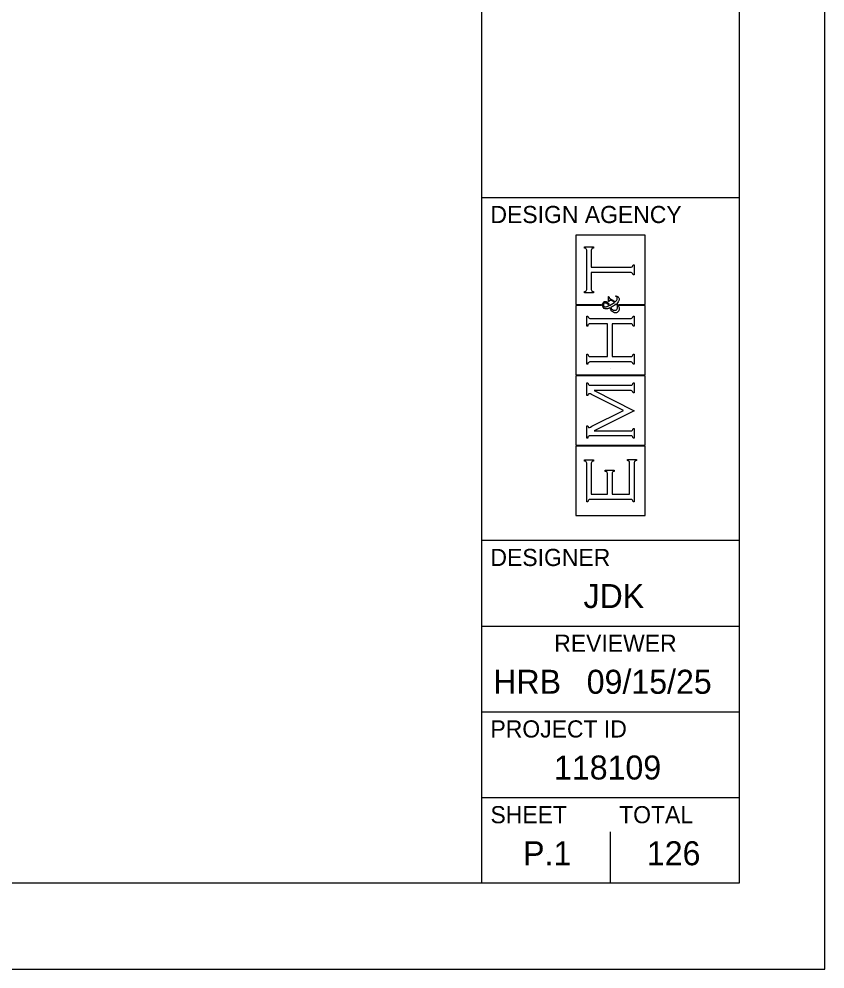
# Model space of a CAD drawing. Extents: x -5.9 to 34, y 0 to 22.
# Drawn here: x 29.3 to 34, y 0 to 5.54 of the extents above; entities that cross this region are included whole.
import ezdxf

# ---------------------------------------------------------------- set-up
doc = ezdxf.new("R2010")
doc.units = 0
for name, color, linetype in [('SH_Border', 7, 'Continuous'), ('SH_Cut_Line', 7, 'Continuous'), ('SH_Data', 7, 'Continuous')]:
    doc.layers.add(name, color=color, linetype=linetype)

msp = doc.modelspace()

# ---------------------------------------------------------------- linework, layer by layer
at = {"layer": 'SH_Border'}
for p, q in [((32, 0.5), (32, 21.5)), ((32, 4.5), (33.5, 4.5)), ((32, 2.5), (33.5, 2.5)), ((32, 2), (33.5, 2)), ((32, 1.5), (33.5, 1.5)), ((32, 1), (33.5, 1))]:
    msp.add_line(p, q, dxfattribs=at)
msp.add_lwpolyline([(1.5, 21.5), (33.5, 21.5), (33.5, 0.5), (1.5, 0.5)], close=True, dxfattribs=at)
at = {"layer": 'SH_Cut_Line'}
msp.add_lwpolyline([(0, 0), (34, 0), (34, 22), (0, 22)], close=True, dxfattribs=at)
at = {"layer": 'SH_Data'}
for p, q in [((32.9517, 4.2794), (32.547, 4.2794)), ((32.547, 4.2794), (32.547, 3.8748)), ((32.9517, 3.8748), (32.9517, 4.2794)), ((32.5978, 4.2041), (32.5978, 4.2106)), ((32.5978, 4.2106), (32.6505, 4.2106)), ((32.6505, 4.2106), (32.6505, 4.2041)), ((32.603, 4.2029), (32.5978, 4.2041)), ((32.6064, 4.2011), (32.603, 4.2029)), ((32.6082, 4.1987), (32.6064, 4.2011)), ((32.6099, 4.1964), (32.6082, 4.1987)), ((32.6108, 4.1924), (32.6099, 4.1964)), ((32.6108, 4.1867), (32.6108, 4.1924)), ((32.6108, 3.9675), (32.6108, 4.1867)), ((32.6383, 4.1964), (32.6375, 4.1924)), ((32.6375, 4.1924), (32.6375, 4.1867)), ((32.6375, 4.1867), (32.6375, 4.093)), ((32.64, 4.1987), (32.6383, 4.1964)), ((32.6418, 4.2011), (32.64, 4.1987)), ((32.6452, 4.2029), (32.6418, 4.2011)), ((32.6505, 4.2041), (32.6452, 4.2029)), ((32.8782, 4.0974), (32.88, 4.1008)), ((32.88, 4.1008), (32.8814, 4.106)), ((32.8814, 4.106), (32.8879, 4.106)), ((32.8879, 4.106), (32.8879, 4.0483)), ((32.6375, 4.093), (32.8639, 4.093)), ((32.8639, 4.0612), (32.6375, 4.0612)), ((32.6375, 4.0612), (32.6375, 3.9676)), ((32.8639, 4.093), (32.8695, 4.093)), ((32.8696, 4.0612), (32.8639, 4.0612)), ((32.8695, 4.093), (32.8734, 4.0939)), ((32.8736, 4.0604), (32.8696, 4.0612)), ((32.8734, 4.0939), (32.8758, 4.0956)), ((32.8759, 4.0586), (32.8736, 4.0604)), ((32.8758, 4.0956), (32.8782, 4.0974)), ((32.8782, 4.0568), (32.8759, 4.0586)), ((32.88, 4.0534), (32.8782, 4.0568)), ((32.8814, 4.0483), (32.88, 4.0534)), ((32.8879, 4.0483), (32.8814, 4.0483)), ((32.5978, 3.9501), (32.603, 3.9513)), ((32.5978, 3.9436), (32.5978, 3.9501)), ((32.6505, 3.9436), (32.5978, 3.9436)), ((32.603, 3.9513), (32.6064, 3.9531)), ((32.6064, 3.9531), (32.6082, 3.9555)), ((32.6082, 3.9555), (32.6099, 3.9579)), ((32.6099, 3.9579), (32.6108, 3.9619)), ((32.6108, 3.9619), (32.6108, 3.9675)), ((32.6375, 3.9676), (32.6375, 3.9619)), ((32.6375, 3.9619), (32.6383, 3.9579)), ((32.6383, 3.9579), (32.6401, 3.9555)), ((32.6401, 3.9555), (32.6418, 3.9531)), ((32.6418, 3.9531), (32.6452, 3.9513)), ((32.6452, 3.9513), (32.6505, 3.9501)), ((32.6505, 3.9501), (32.6505, 3.9436)), ((32.7035, 3.8788), (32.7051, 3.8832)), ((32.7035, 3.8734), (32.7035, 3.8788)), ((32.7051, 3.8832), (32.7082, 3.8866)), ((32.7082, 3.8866), (32.7114, 3.89)), ((32.7094, 3.8787), (32.7083, 3.8762)), ((32.7115, 3.8807), (32.7094, 3.8787)), ((32.7114, 3.89), (32.7153, 3.8917)), ((32.7137, 3.8827), (32.7115, 3.8807)), ((32.7164, 3.8837), (32.7137, 3.8827)), ((32.7153, 3.8917), (32.7199, 3.8917)), ((32.7196, 3.8837), (32.7164, 3.8837)), ((32.7238, 3.8837), (32.7196, 3.8837)), ((32.7199, 3.8917), (32.7247, 3.8917)), ((32.7276, 3.8823), (32.7238, 3.8837)), ((32.7247, 3.8917), (32.7289, 3.89)), ((32.731, 3.8795), (32.7276, 3.8823)), ((32.7289, 3.89), (32.7325, 3.8867)), ((32.7344, 3.8767), (32.731, 3.8795)), ((32.7325, 3.8867), (32.7361, 3.8834)), ((32.7361, 3.8834), (32.74, 3.8775)), ((32.7383, 3.8931), (32.7383, 3.9216)), ((32.7383, 3.9216), (32.7408, 3.9216)), ((32.7408, 3.8931), (32.7383, 3.8931)), ((32.7408, 3.9216), (32.7411, 3.9177)), ((32.741, 3.895), (32.7408, 3.8931)), ((32.7418, 3.8964), (32.741, 3.895)), ((32.7411, 3.9177), (32.742, 3.9148)), ((32.743, 3.8974), (32.7418, 3.8964)), ((32.742, 3.9148), (32.7434, 3.9129)), ((32.7446, 3.8987), (32.743, 3.8974)), ((32.7434, 3.9129), (32.7448, 3.911)), ((32.7464, 3.8994), (32.7446, 3.8987)), ((32.7448, 3.911), (32.7491, 3.9081)), ((32.7485, 3.8994), (32.7464, 3.8994)), ((32.7549, 3.8994), (32.7485, 3.8994)), ((32.7491, 3.9081), (32.7562, 3.9041)), ((32.7545, 3.8751), (32.7638, 3.8812)), ((32.7629, 3.8954), (32.7549, 3.8994)), ((32.7562, 3.9041), (32.7634, 3.9001)), ((32.7723, 3.8874), (32.7629, 3.8954)), ((32.7634, 3.9001), (32.77, 3.8956)), ((32.7638, 3.8812), (32.7723, 3.8874)), ((32.77, 3.8956), (32.7762, 3.8905)), ((32.7762, 3.8905), (32.7809, 3.8945)), ((32.7788, 3.9232), (32.7806, 3.9258)), ((32.7821, 3.9224), (32.7788, 3.9232)), ((32.7806, 3.9258), (32.787, 3.9241)), ((32.7809, 3.8945), (32.7841, 3.8981)), ((32.7846, 3.9208), (32.7821, 3.9224)), ((32.7841, 3.8981), (32.786, 3.9013)), ((32.7863, 3.9187), (32.7846, 3.9208)), ((32.786, 3.9013), (32.7879, 3.9044)), ((32.7909, 3.8856), (32.786, 3.8811)), ((32.786, 3.8811), (32.7911, 3.8755)), ((32.7879, 3.9165), (32.7863, 3.9187)), ((32.787, 3.9241), (32.7917, 3.9214)), ((32.7888, 3.9139), (32.7879, 3.9165)), ((32.7879, 3.9044), (32.7888, 3.9076)), ((32.7888, 3.9108), (32.7888, 3.9139)), ((32.7888, 3.9076), (32.7888, 3.9108)), ((32.7943, 3.8898), (32.7909, 3.8856)), ((32.7917, 3.9214), (32.7948, 3.9177)), ((32.7964, 3.8936), (32.7943, 3.8898)), ((32.7948, 3.9177), (32.7979, 3.914)), ((32.7984, 3.8974), (32.7964, 3.8936)), ((32.7979, 3.914), (32.7994, 3.9097)), ((32.7994, 3.9011), (32.7984, 3.8974)), ((32.7994, 3.9097), (32.7994, 3.9048)), ((32.7994, 3.9048), (32.7994, 3.9011)), ((32.547, 3.8748), (32.6961, 3.8748)), ((32.6956, 3.8694), (32.5471, 3.8694)), ((32.5471, 3.8694), (32.5471, 3.4648)), ((32.6961, 3.8748), (32.6956, 3.8694)), ((32.7035, 3.8678), (32.7035, 3.8734)), ((32.705, 3.8628), (32.7035, 3.8678)), ((32.7082, 3.8583), (32.705, 3.8628)), ((32.7123, 3.8526), (32.7082, 3.8583)), ((32.7083, 3.8762), (32.7083, 3.8732)), ((32.7083, 3.8732), (32.7083, 3.8693)), ((32.7083, 3.8693), (32.7097, 3.8664)), ((32.7097, 3.8664), (32.7125, 3.8644)), ((32.7182, 3.8498), (32.7123, 3.8526)), ((32.7125, 3.8644), (32.7152, 3.8623)), ((32.7152, 3.8623), (32.7179, 3.8614)), ((32.7179, 3.8614), (32.7205, 3.8614)), ((32.7259, 3.8498), (32.7182, 3.8498)), ((32.7205, 3.8614), (32.7227, 3.8614)), ((32.7227, 3.8614), (32.7252, 3.8617)), ((32.7252, 3.8617), (32.7279, 3.8625)), ((32.7286, 3.8498), (32.7259, 3.8498)), ((32.7279, 3.8625), (32.7307, 3.8632)), ((32.7315, 3.8502), (32.7286, 3.8498)), ((32.7307, 3.8632), (32.7347, 3.8647)), ((32.7345, 3.8509), (32.7315, 3.8502)), ((32.7374, 3.8725), (32.7344, 3.8767)), ((32.7375, 3.8517), (32.7345, 3.8509)), ((32.7347, 3.8647), (32.7401, 3.8668)), ((32.7401, 3.8668), (32.7374, 3.8725)), ((32.7413, 3.8531), (32.7375, 3.8517)), ((32.74, 3.8775), (32.7443, 3.8691)), ((32.746, 3.8552), (32.7413, 3.8531)), ((32.7443, 3.8691), (32.7545, 3.8751)), ((32.7519, 3.8444), (32.746, 3.8552)), ((32.7561, 3.8603), (32.7505, 3.8575)), ((32.7505, 3.8575), (32.7537, 3.8521)), ((32.7575, 3.837), (32.7519, 3.8444)), ((32.7537, 3.8521), (32.7571, 3.8481)), ((32.7607, 3.8628), (32.7561, 3.8603)), ((32.7571, 3.8481), (32.7609, 3.8454)), ((32.7629, 3.8331), (32.7575, 3.837)), ((32.7644, 3.8651), (32.7607, 3.8628)), ((32.7609, 3.8454), (32.7646, 3.8427)), ((32.7684, 3.8292), (32.7629, 3.8331)), ((32.7681, 3.8674), (32.7644, 3.8651)), ((32.7646, 3.8427), (32.7687, 3.8413)), ((32.7741, 3.8716), (32.7681, 3.8674)), ((32.7738, 3.8273), (32.7684, 3.8292)), ((32.7687, 3.8413), (32.7731, 3.8413)), ((32.7731, 3.8413), (32.7779, 3.8413)), ((32.7793, 3.8273), (32.7738, 3.8273)), ((32.7821, 3.8776), (32.7741, 3.8716)), ((32.7779, 3.8413), (32.7822, 3.8429)), ((32.7848, 3.8273), (32.7793, 3.8273)), ((32.7859, 3.873), (32.7821, 3.8776)), ((32.7822, 3.8429), (32.7858, 3.846)), ((32.7895, 3.8294), (32.7848, 3.8273)), ((32.7858, 3.846), (32.7895, 3.8491)), ((32.7884, 3.8694), (32.7859, 3.873)), ((32.7896, 3.8668), (32.7884, 3.8694)), ((32.7895, 3.8491), (32.7913, 3.8533)), ((32.7935, 3.8338), (32.7895, 3.8294)), ((32.7907, 3.8642), (32.7896, 3.8668)), ((32.7913, 3.8614), (32.7907, 3.8642)), ((32.7911, 3.8755), (32.7946, 3.8705)), ((32.7913, 3.8586), (32.7913, 3.8614)), ((32.7913, 3.8533), (32.7913, 3.8586)), ((32.7975, 3.8382), (32.7935, 3.8338)), ((32.7946, 3.8705), (32.7965, 3.866)), ((32.7965, 3.866), (32.7985, 3.8615)), ((32.7994, 3.8441), (32.7975, 3.8382)), ((32.7985, 3.8615), (32.7994, 3.8567)), ((32.8029, 3.8694), (32.799, 3.8748)), ((32.799, 3.8748), (32.9517, 3.8748)), ((32.7994, 3.8567), (32.7994, 3.8516)), ((32.7994, 3.8516), (32.7994, 3.8441)), ((32.9517, 3.8694), (32.8029, 3.8694)), ((32.9517, 3.4648), (32.9517, 3.8694)), ((32.6108, 3.7493), (32.6108, 3.8071)), ((32.6108, 3.8071), (32.6173, 3.8071)), ((32.6173, 3.8071), (32.6186, 3.8019)), ((32.6186, 3.8019), (32.6205, 3.7985)), ((32.6205, 3.7985), (32.6228, 3.7967)), ((32.6228, 3.7967), (32.6251, 3.7949)), ((32.6251, 3.7949), (32.629, 3.7941)), ((32.629, 3.7941), (32.6347, 3.7941)), ((32.6347, 3.7941), (32.8639, 3.7941)), ((32.8639, 3.7941), (32.8695, 3.7941)), ((32.8695, 3.7941), (32.8734, 3.7949)), ((32.8734, 3.7949), (32.8758, 3.7967)), ((32.8758, 3.7967), (32.8782, 3.7985)), ((32.8782, 3.7985), (32.88, 3.8019)), ((32.88, 3.8019), (32.8814, 3.8071)), ((32.8814, 3.8071), (32.8879, 3.8071)), ((32.8879, 3.8071), (32.8879, 3.7493)), ((32.6173, 3.7493), (32.6108, 3.7493)), ((32.6185, 3.7545), (32.6173, 3.7493)), ((32.6203, 3.7579), (32.6185, 3.7545)), ((32.6227, 3.7597), (32.6203, 3.7579)), ((32.625, 3.7614), (32.6227, 3.7597)), ((32.629, 3.7623), (32.625, 3.7614)), ((32.6347, 3.7623), (32.629, 3.7623)), ((32.732, 3.7623), (32.6347, 3.7623)), ((32.732, 3.5718), (32.732, 3.7623)), ((32.8639, 3.7623), (32.7587, 3.7623)), ((32.7587, 3.7623), (32.7587, 3.5718)), ((32.8696, 3.7623), (32.8639, 3.7623)), ((32.8736, 3.7614), (32.8696, 3.7623)), ((32.8759, 3.7597), (32.8736, 3.7614)), ((32.8782, 3.7579), (32.8759, 3.7597)), ((32.88, 3.7545), (32.8782, 3.7579)), ((32.8814, 3.7493), (32.88, 3.7545)), ((32.8879, 3.7493), (32.8814, 3.7493)), ((32.6108, 3.5271), (32.6108, 3.5848)), ((32.6108, 3.5848), (32.6173, 3.5848)), ((32.6173, 3.5848), (32.6186, 3.5797)), ((32.6186, 3.5797), (32.6205, 3.5762)), ((32.6205, 3.5762), (32.6228, 3.5745)), ((32.6228, 3.5745), (32.6251, 3.5727)), ((32.6251, 3.5727), (32.629, 3.5718)), ((32.629, 3.5718), (32.6347, 3.5718)), ((32.6347, 3.5718), (32.732, 3.5718)), ((32.7587, 3.5718), (32.8639, 3.5718)), ((32.8639, 3.5718), (32.8696, 3.5718)), ((32.8696, 3.5718), (32.8736, 3.5727)), ((32.8736, 3.5727), (32.8759, 3.5744)), ((32.8759, 3.5744), (32.8782, 3.576)), ((32.8782, 3.576), (32.88, 3.5795)), ((32.88, 3.5795), (32.8814, 3.5848)), ((32.8814, 3.5848), (32.8879, 3.5848)), ((32.8879, 3.5848), (32.8879, 3.5271)), ((32.6173, 3.5271), (32.6108, 3.5271)), ((32.6185, 3.5322), (32.6173, 3.5271)), ((32.6203, 3.5357), (32.6185, 3.5322)), ((32.6227, 3.5374), (32.6203, 3.5357)), ((32.625, 3.5392), (32.6227, 3.5374)), ((32.6291, 3.5401), (32.625, 3.5392)), ((32.6347, 3.5401), (32.6291, 3.5401)), ((32.8639, 3.5401), (32.6347, 3.5401)), ((32.75, 3.5), (32.75, 3.5)), ((32.8696, 3.5401), (32.8639, 3.5401)), ((32.8736, 3.5392), (32.8696, 3.5401)), ((32.8759, 3.5375), (32.8736, 3.5392)), ((32.8782, 3.5358), (32.8759, 3.5375)), ((32.88, 3.5324), (32.8782, 3.5358)), ((32.8814, 3.5271), (32.88, 3.5324)), ((32.8879, 3.5271), (32.8814, 3.5271)), ((32.9516, 3.4593), (32.547, 3.4593)), ((32.547, 3.4593), (32.547, 3.0547)), ((32.5471, 3.4648), (32.9517, 3.4648)), ((32.9517, 3.0547), (32.9516, 3.4593)), ((32.6108, 3.3452), (32.6108, 3.4176)), ((32.6108, 3.4176), (32.6173, 3.4176)), ((32.6173, 3.4176), (32.6186, 3.4124)), ((32.6186, 3.4124), (32.6205, 3.409)), ((32.6205, 3.409), (32.6228, 3.4072)), ((32.6228, 3.4072), (32.6251, 3.4055)), ((32.6251, 3.4055), (32.6291, 3.4046)), ((32.6291, 3.4046), (32.6347, 3.4046)), ((32.6347, 3.4046), (32.8639, 3.4046)), ((32.8639, 3.4046), (32.8695, 3.4046)), ((32.8695, 3.4046), (32.8734, 3.4055)), ((32.8734, 3.4055), (32.8758, 3.4072)), ((32.8758, 3.4072), (32.8782, 3.409)), ((32.8782, 3.409), (32.88, 3.4124)), ((32.88, 3.4124), (32.8814, 3.4176)), ((32.8814, 3.4176), (32.8879, 3.4176)), ((32.8879, 3.4176), (32.8879, 3.3598)), ((32.6173, 3.3452), (32.6108, 3.3452)), ((32.6196, 3.3518), (32.6173, 3.3452)), ((32.6225, 3.3551), (32.6196, 3.3518)), ((32.626, 3.3551), (32.6225, 3.3551)), ((32.6287, 3.3551), (32.626, 3.3551)), ((32.6333, 3.3535), (32.6287, 3.3551)), ((32.6398, 3.3502), (32.6333, 3.3535)), ((32.8253, 3.2574), (32.6398, 3.3502)), ((32.8639, 3.3728), (32.6543, 3.3728)), ((32.6543, 3.3728), (32.8879, 3.2548)), ((32.8696, 3.3728), (32.8639, 3.3728)), ((32.8736, 3.372), (32.8696, 3.3728)), ((32.8759, 3.3703), (32.8736, 3.372)), ((32.8782, 3.3686), (32.8759, 3.3703)), ((32.88, 3.3651), (32.8782, 3.3686)), ((32.8814, 3.3598), (32.88, 3.3651)), ((32.8879, 3.3598), (32.8814, 3.3598)), ((32.6414, 3.165), (32.8253, 3.2574)), ((32.8879, 3.2548), (32.6543, 3.1383)), ((32.6108, 3.0965), (32.6108, 3.1682)), ((32.6108, 3.1682), (32.6173, 3.1682)), ((32.6173, 3.1682), (32.6196, 3.1616)), ((32.6196, 3.1616), (32.6224, 3.1583)), ((32.6224, 3.1583), (32.6258, 3.1583)), ((32.6258, 3.1583), (32.6274, 3.1583)), ((32.6274, 3.1583), (32.6326, 3.1605)), ((32.6326, 3.1605), (32.6414, 3.165)), ((32.6203, 3.105), (32.6185, 3.1016)), ((32.6227, 3.1068), (32.6203, 3.105)), ((32.625, 3.1086), (32.6227, 3.1068)), ((32.6291, 3.1094), (32.625, 3.1086)), ((32.6347, 3.1094), (32.6291, 3.1094)), ((32.8639, 3.1095), (32.6347, 3.1094)), ((32.6543, 3.1383), (32.8639, 3.1383)), ((32.8639, 3.1383), (32.8694, 3.1383)), ((32.8696, 3.1095), (32.8639, 3.1095)), ((32.8694, 3.1383), (32.8734, 3.1392)), ((32.8736, 3.1086), (32.8696, 3.1095)), ((32.8734, 3.1392), (32.8758, 3.141)), ((32.8759, 3.1068), (32.8736, 3.1086)), ((32.8758, 3.141), (32.8782, 3.1427)), ((32.8782, 3.1051), (32.8759, 3.1068)), ((32.8782, 3.1427), (32.88, 3.1462)), ((32.88, 3.1016), (32.8782, 3.1051)), ((32.88, 3.1462), (32.8814, 3.1513)), ((32.8814, 3.1513), (32.8879, 3.1513)), ((32.8879, 3.1513), (32.8879, 3.0965)), ((32.547, 3.0547), (32.9517, 3.0547)), ((32.9517, 3.0493), (32.547, 3.0492)), ((32.547, 3.0492), (32.547, 2.6447)), ((32.6173, 3.0965), (32.6108, 3.0965)), ((32.6185, 3.1016), (32.6173, 3.0965)), ((32.8814, 3.0965), (32.88, 3.1016)), ((32.8879, 3.0965), (32.8814, 3.0965)), ((32.9517, 2.6447), (32.9517, 3.0493)), ((32.5978, 2.9624), (32.5978, 2.9689)), ((32.5978, 2.9689), (32.6505, 2.9689)), ((32.603, 2.9611), (32.5978, 2.9624)), ((32.6065, 2.9592), (32.603, 2.9611)), ((32.6082, 2.9569), (32.6065, 2.9592)), ((32.61, 2.9546), (32.6082, 2.9569)), ((32.6108, 2.9506), (32.61, 2.9546)), ((32.6108, 2.9449), (32.6108, 2.9506)), ((32.6108, 2.725), (32.6108, 2.9449)), ((32.6384, 2.9546), (32.6375, 2.9506)), ((32.6375, 2.9506), (32.6375, 2.9449)), ((32.6375, 2.9449), (32.6375, 2.7697)), ((32.6402, 2.957), (32.6384, 2.9546)), ((32.642, 2.9594), (32.6402, 2.957)), ((32.6454, 2.9612), (32.642, 2.9594)), ((32.6505, 2.9624), (32.6454, 2.9612)), ((32.6505, 2.9689), (32.6505, 2.9624)), ((32.8482, 2.9653), (32.8482, 2.9718)), ((32.8482, 2.9718), (32.9009, 2.9718)), ((32.8533, 2.9641), (32.8482, 2.9653)), ((32.8568, 2.9623), (32.8533, 2.9641)), ((32.8586, 2.9599), (32.8568, 2.9623)), ((32.8603, 2.9575), (32.8586, 2.9599)), ((32.8612, 2.9535), (32.8603, 2.9575)), ((32.8612, 2.9478), (32.8612, 2.9535)), ((32.8612, 2.7697), (32.8612, 2.9478)), ((32.8888, 2.9573), (32.8879, 2.9533)), ((32.8879, 2.9533), (32.8879, 2.9476)), ((32.8879, 2.9476), (32.8879, 2.725)), ((32.8905, 2.9597), (32.8888, 2.9573)), ((32.8923, 2.9621), (32.8905, 2.9597)), ((32.8957, 2.9639), (32.8923, 2.9621)), ((32.9009, 2.9653), (32.8957, 2.9639)), ((32.9009, 2.9718), (32.9009, 2.9653)), ((32.719, 2.9018), (32.719, 2.9083)), ((32.719, 2.9083), (32.7717, 2.9083)), ((32.7242, 2.9006), (32.719, 2.9018)), ((32.7276, 2.8988), (32.7242, 2.9006)), ((32.7294, 2.8964), (32.7276, 2.8988)), ((32.7312, 2.894), (32.7294, 2.8964)), ((32.732, 2.89), (32.7312, 2.894)), ((32.732, 2.8844), (32.732, 2.89)), ((32.732, 2.7697), (32.732, 2.8844)), ((32.7596, 2.894), (32.7587, 2.89)), ((32.7587, 2.89), (32.7587, 2.8844)), ((32.7587, 2.8844), (32.7587, 2.7697)), ((32.7614, 2.8964), (32.7596, 2.894)), ((32.7631, 2.8988), (32.7614, 2.8964)), ((32.7666, 2.9006), (32.7631, 2.8988)), ((32.7717, 2.9018), (32.7666, 2.9006)), ((32.7717, 2.9083), (32.7717, 2.9018)), ((32.6173, 2.725), (32.6108, 2.725)), ((32.6187, 2.7301), (32.6173, 2.725)), ((32.6205, 2.7336), (32.6187, 2.7301)), ((32.6228, 2.7354), (32.6205, 2.7336)), ((32.6251, 2.7371), (32.6228, 2.7354)), ((32.6291, 2.738), (32.6251, 2.7371)), ((32.6348, 2.738), (32.6291, 2.738)), ((32.864, 2.738), (32.6348, 2.738)), ((32.6375, 2.7697), (32.732, 2.7697)), ((32.7587, 2.7697), (32.8612, 2.7697)), ((32.8696, 2.738), (32.864, 2.738)), ((32.8736, 2.7372), (32.8696, 2.738)), ((32.8759, 2.7355), (32.8736, 2.7372)), ((32.8782, 2.7338), (32.8759, 2.7355)), ((32.88, 2.7303), (32.8782, 2.7338)), ((32.8814, 2.725), (32.88, 2.7303)), ((32.8879, 2.725), (32.8814, 2.725)), ((32.547, 2.6447), (32.9517, 2.6447)), ((32.75, 0.5), (32.75, 0.8)), ((32.375, 0.675), (32.375, 0.675))]:
    msp.add_line(p, q, dxfattribs=at)

# ---------------------------------------------------------------- texts
for s, height, p in [('DESIGN AGENCY', 0.1, (32.05, 4.35)), ('DESIGNER', 0.1, (32.05, 2.35)), ('JDK', 0.14, (32.5923, 2.105)), ('REVIEWER', 0.1, (32.4218, 1.85)), ('HRB', 0.14, (32.0662, 1.605)), ('09/15/25', 0.14, (32.611, 1.605)), ('PROJECT ID', 0.1, (32.05, 1.35)), ('118109', 0.14, (32.4204, 1.105)), ('SHEET', 0.1, (32.05, 0.85)), ('TOTAL', 0.1, (32.8, 0.85)), ('P.1', 0.14, (32.2403, 0.605)), ('126', 0.14, (32.9617, 0.605))]:
    msp.add_text(s, height=height, dxfattribs=at).set_placement(p)

doc.saveas('drawing.dxf')
